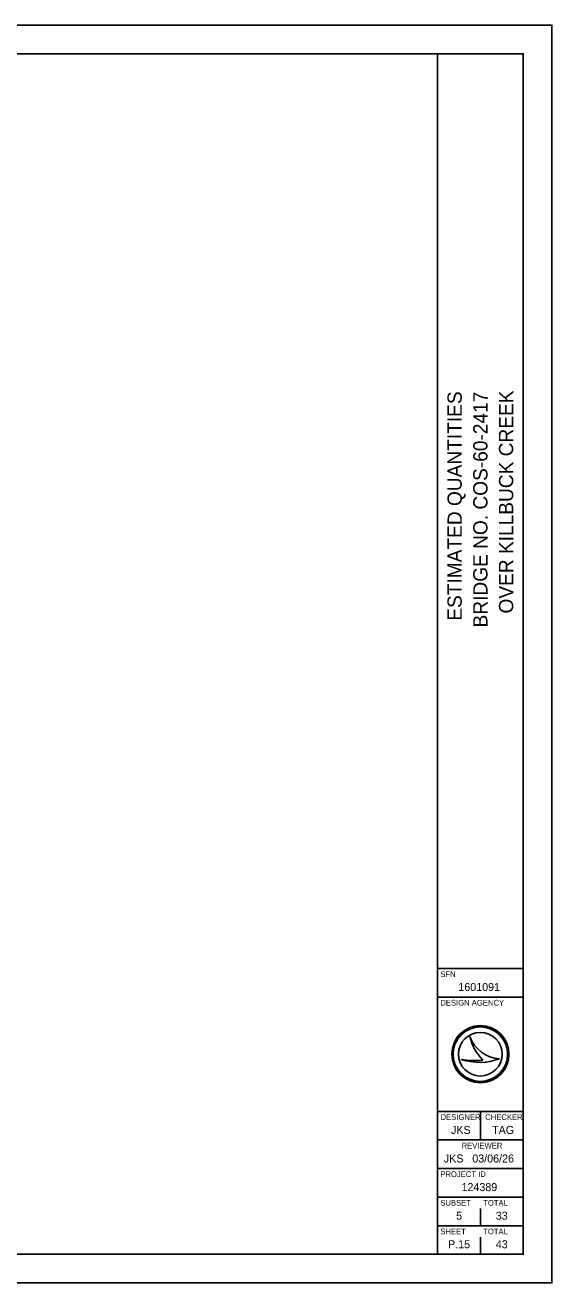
# Model space of a CAD drawing. Extents: x 0 to 34, y 0 to 22.
# Drawn here: x 24.79 to 34, y 0 to 22 of the extents above; entities that cross this region are included whole.
import ezdxf

# ---------------------------------------------------------------- set-up
doc = ezdxf.new("R2010")
doc.units = 0
for name, color, linetype in [('SH_Border', 7, 'Continuous'), ('SH_Cut_Line', 7, 'Continuous'), ('SH_Data', 7, 'Continuous')]:
    doc.layers.add(name, color=color, linetype=linetype)

msp = doc.modelspace()

# ---------------------------------------------------------------- linework, layer by layer
at = {"layer": 'SH_Border'}
for p, q in [((32, 0.5), (32, 21.5)), ((32, 5.5), (33.5, 5.5)), ((32, 5), (33.5, 5)), ((32, 3), (33.5, 3)), ((32.75, 3), (32.75, 2.5)), ((32, 2.5), (33.5, 2.5)), ((32, 2), (33.5, 2)), ((32, 1.5), (33.5, 1.5)), ((32, 1), (33.5, 1))]:
    msp.add_line(p, q, dxfattribs=at)
msp.add_lwpolyline([(1.5, 21.5), (33.5, 21.5), (33.5, 0.5), (1.5, 0.5)], close=True, dxfattribs=at)
at = {"layer": 'SH_Cut_Line'}
msp.add_lwpolyline([(0, 0), (34, 0), (34, 22), (0, 22)], close=True, dxfattribs=at)
at = {"layer": 'SH_Data'}
for p, q in [((32.567, 4.31), (32.567, 4.31)), ((32.75, 4), (32.75, 4)), ((32.417, 3.91), (32.417, 3.91)), ((33.087, 3.919), (33.087, 3.919)), ((32.75, 1), (32.75, 1.3)), ((32.375, 0.675), (32.375, 0.675)), ((32.75, 0.5), (32.75, 0.8))]:
    msp.add_line(p, q, dxfattribs=at)
for radius in [0.5, 0.477, 0.477, 0.382]:
    msp.add_circle((32.75, 4), radius, dxfattribs=at)
for centre, radius, start, end in [((33.116, 4.498), 0.58, 198.9257, 198.9319), ((33.347, 4.47), 0.796, 191.6379, 191.6421), ((33.116, 4.498), 0.58, 198.9319, 267.1657), ((33.347, 4.47), 0.796, 191.6421, 226.0947), ((32.739, 4.87), 1.013, 251.4576, 290.0832), ((32.648, 5.154), 1.266, 259.4964, 259.4995), ((32.739, 4.87), 1.013, 251.4527, 251.4576), ((32.648, 5.154), 1.266, 259.4995, 276.6672)]:
    msp.add_arc(centre, radius, start, end, dxfattribs=at)

# ---------------------------------------------------------------- texts
for s, p in [('ESTIMATED QUANTITIES', (32.425, 11.582)), ('BRIDGE NO. COS-60-2417', (32.875, 11.464)), ('OVER KILLBUCK CREEK', (33.325, 11.708))]:
    msp.add_text(s, height=0.25, rotation=90, dxfattribs=at).set_placement(p)
for s, height, p in [('SFN', 0.1, (32.05, 5.35)), ('1601091', 0.14, (32.365, 5.105)), ('DESIGN AGENCY', 0.1, (32.05, 4.85)), ('DESIGNER', 0.1, (32.054, 2.85)), ('CHECKER', 0.1, (32.835, 2.85)), ('JKS', 0.14, (32.237, 2.605)), ('TAG', 0.14, (32.955, 2.605)), ('REVIEWER', 0.1, (32.422, 2.35)), ('JKS', 0.14, (32.112, 2.105)), ('03/06/26', 0.14, (32.609, 2.105)), ('PROJECT ID', 0.1, (32.05, 1.85)), ('124389', 0.14, (32.42, 1.605)), ('SUBSET', 0.1, (32.05, 1.35)), ('TOTAL', 0.1, (32.8, 1.35)), ('5', 0.14, (32.326, 1.105)), ('33', 0.14, (33.02, 1.105)), ('SHEET', 0.1, (32.05, 0.85)), ('TOTAL', 0.1, (32.8, 0.85)), ('P.15', 0.14, (32.185, 0.605)), ('43', 0.14, (33.02, 0.605))]:
    msp.add_text(s, height=height, dxfattribs=at).set_placement(p)

doc.saveas('drawing.dxf')
